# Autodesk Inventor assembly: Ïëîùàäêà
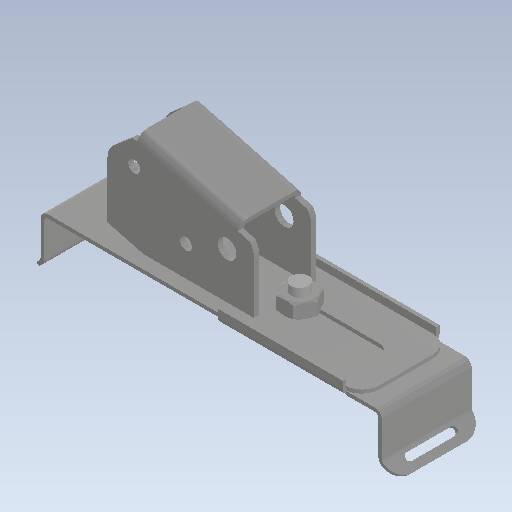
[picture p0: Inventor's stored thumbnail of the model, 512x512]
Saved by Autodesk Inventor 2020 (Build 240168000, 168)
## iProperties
Created: 1900-01
Part Number: Ïëîùàäêà
Document SubType Name: Assembly
Designer: bruno
Author: bruno
Revision Number: ANYUNSPECIFIED
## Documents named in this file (5)
- C:\Users\bruno\Documents\1-Cours-2022-23\1SI\2. Cinématique\Hoverboard\Inventor-Hoverboard\Articulation.iam
- C:\Users\bruno\Documents\1-Cours-2022-23\1SI\2. Cinématique\Hoverboard\Inventor-Hoverboard\Equerre.ipt
- C:\Users\bruno\Documents\1-Cours-2022-23\1SI\2. Cinématique\Hoverboard\Inventor-Hoverboard\Articulation-2.ipt
- C:\Users\bruno\Documents\1-Cours-2022-23\1SI\2. Cinématique\Hoverboard\Inventor-Hoverboard\Platine-male.iam
- C:\Users\bruno\Documents\1-Cours-2022-23\1SI\2. Cinématique\Hoverboard\Inventor-Hoverboard\Ecrou.ipt
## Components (4 placed, 4 different names)
1. 15
2. 16
3. 19 [sub-assembly]
4. 20
